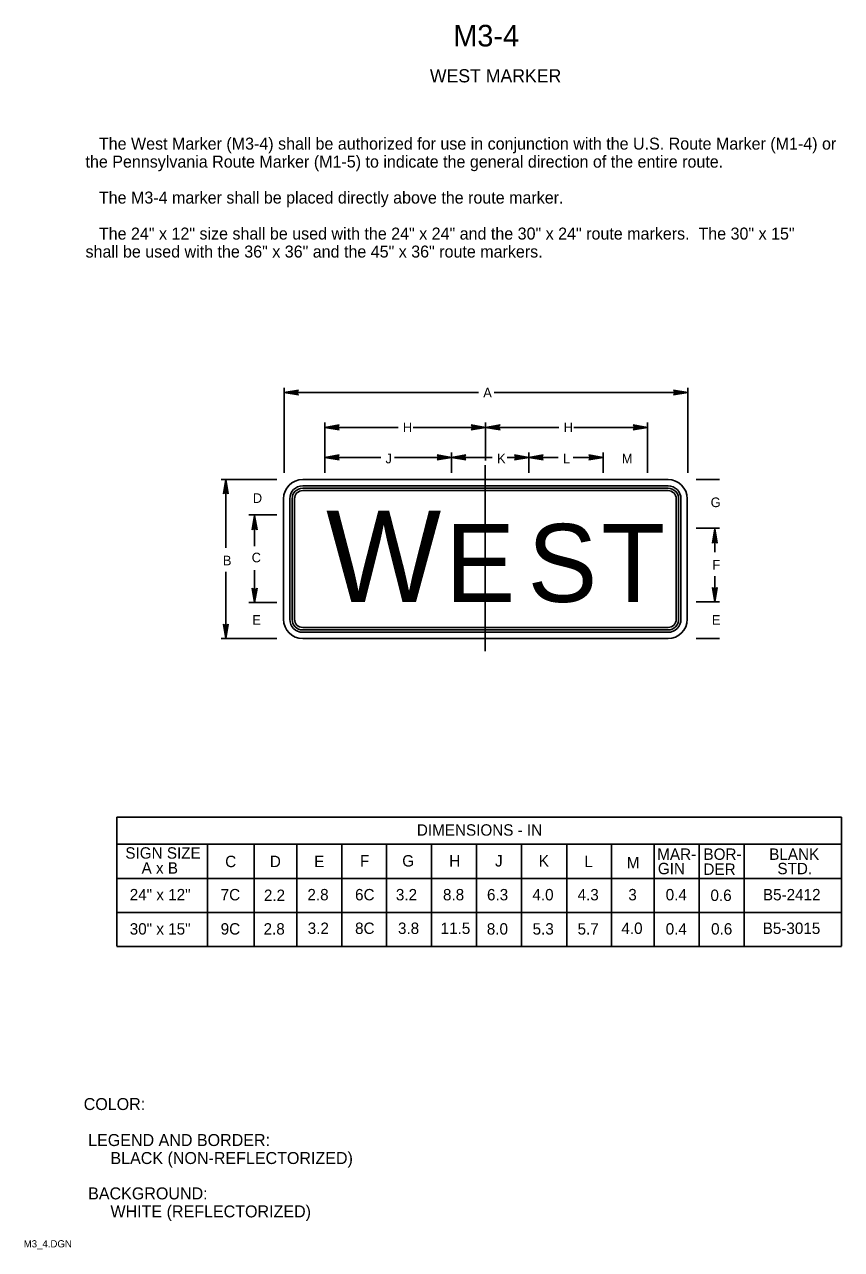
# Model space of a CAD drawing. Extents: x 0.013 to 0.183, y 0.004 to 0.259.
import ezdxf

# ---------------------------------------------------------------- set-up
doc = ezdxf.new("R2010")
doc.units = 0
doc.layers.add('1', color=7, linetype='Continuous')
doc.layers.add('3', color=7, linetype='Continuous')

# ---------------------------------------------------------------- blocks, each defined once
blk = doc.blocks.new('RARROW')
at = {"layer": '3'}
for p, q in [((-2.156, 0.285), (-2.2665, 0.384625)), ((-2.2665, 0.384625), (0, 0)), ((0, 0), (-2.2665, -0.379125)), ((-2.156, 0.285), (-2.075625, 0.12075)), ((0, 0), (-2.156, 0.285)), ((-2.14975, -0.2705), (0, 0)), ((-2.075625, 0.12075), (0, 0)), ((0, 0), (-2.074, -0.108)), ((-2.2665, -0.379125), (-2.14975, -0.2705)), ((-2.074, -0.108), (-2.14975, -0.2705))]:
    blk.add_line(p, q, dxfattribs=at)

msp = doc.modelspace()

# ---------------------------------------------------------------- linework, layer by layer
at = {"layer": '3'}
for p, q in [((0.06675, 0.16575), (0.06675, 0.1835)), ((0.10725, 0.1825), (0.06675, 0.1825)), ((0.1105, 0.1825), (0.15088, 0.1825)), ((0.15088, 0.16575), (0.15088, 0.1835)), ((0.07525, 0.16575), (0.07525, 0.17625)), ((0.10875, 0.16837), (0.10875, 0.17625)), ((0.1425, 0.16575), (0.1425, 0.17625)), ((0.0905, 0.17525), (0.07525, 0.17525)), ((0.09362, 0.17525), (0.10875, 0.17525)), ((0.124, 0.17525), (0.10875, 0.17525)), ((0.12713, 0.17525), (0.1425, 0.17525)), ((0.08688, 0.169), (0.07525, 0.169)), ((0.08975, 0.169), (0.10163, 0.169)), ((0.10163, 0.16575), (0.10163, 0.17)), ((0.11013, 0.169), (0.10163, 0.169)), ((0.11325, 0.169), (0.11775, 0.169)), ((0.11775, 0.16575), (0.11775, 0.17)), ((0.12387, 0.169), (0.11775, 0.169)), ((0.127, 0.169), (0.13325, 0.169)), ((0.12925, 0.169), (0.13325, 0.169)), ((0.13325, 0.16575), (0.13325, 0.17)), ((0.10862, 0.16737), (0.10862, 0.12862)), ((0.06525, 0.16437), (0.05362, 0.16437)), ((0.05462, 0.15013), (0.05462, 0.16437)), ((0.07063, 0.16437), (0.14675, 0.16437)), ((0.15263, 0.16437), (0.1575, 0.16437)), ((0.07063, 0.16307), (0.14675, 0.16307)), ((0.07063, 0.16257), (0.14675, 0.16257)), ((0.07063, 0.16207), (0.14675, 0.16207)), ((0.06663, 0.13525), (0.06663, 0.16037)), ((0.06793, 0.13525), (0.06793, 0.16037)), ((0.06843, 0.13525), (0.06843, 0.16037)), ((0.06893, 0.13525), (0.06893, 0.16037)), ((0.14845, 0.16037), (0.14845, 0.13525)), ((0.14895, 0.16037), (0.14895, 0.13525)), ((0.14945, 0.16037), (0.14945, 0.13525)), ((0.15075, 0.16037), (0.15075, 0.13525)), ((0.06525, 0.157), (0.05938, 0.157)), ((0.06062, 0.153), (0.06062, 0.157)), ((0.06062, 0.1505), (0.06062, 0.157)), ((0.15263, 0.15425), (0.1575, 0.15425)), ((0.1565, 0.15038), (0.1565, 0.15438)), ((0.1565, 0.14925), (0.1565, 0.15425)), ((0.06062, 0.1455), (0.06062, 0.13887)), ((0.05462, 0.14513), (0.05462, 0.13125)), ((0.1565, 0.14425), (0.1565, 0.139)), ((0.1565, 0.143), (0.1565, 0.139)), ((0.06062, 0.14288), (0.06062, 0.13887)), ((0.06525, 0.13875), (0.05938, 0.13875)), ((0.15263, 0.13887), (0.1575, 0.13887)), ((0.14675, 0.13355), (0.07063, 0.13355)), ((0.14675, 0.13305), (0.07063, 0.13305)), ((0.06525, 0.13125), (0.05362, 0.13125)), ((0.06475, 0.13125), (0.05963, 0.13125)), ((0.14675, 0.13255), (0.07063, 0.13255)), ((0.14675, 0.13125), (0.07063, 0.13125)), ((0.15263, 0.13125), (0.1575, 0.13125)), ((0.03187, 0.094), (0.18288, 0.094)), ((0.03187, 0.094), (0.03187, 0.06713)), ((0.18288, 0.094), (0.18288, 0.06713)), ((0.18289, 0.08838), (0.03189, 0.08838)), ((0.05077, 0.08838), (0.05077, 0.06708)), ((0.0605, 0.08837), (0.0605, 0.06713)), ((0.06938, 0.08837), (0.06938, 0.06713)), ((0.07875, 0.08837), (0.07875, 0.06713)), ((0.08812, 0.08837), (0.08812, 0.06713)), ((0.0975, 0.08837), (0.0975, 0.06713)), ((0.10687, 0.08837), (0.10687, 0.06713)), ((0.11625, 0.08837), (0.11625, 0.06713)), ((0.12563, 0.08837), (0.12563, 0.06713)), ((0.135, 0.08837), (0.135, 0.06713)), ((0.14389, 0.08838), (0.14389, 0.06708)), ((0.15327, 0.08838), (0.15327, 0.06708)), ((0.16264, 0.08838), (0.16264, 0.06708)), ((0.18288, 0.08128), (0.03187, 0.08128)), ((0.18289, 0.07418), (0.03189, 0.07418)), ((0.18289, 0.06708), (0.03189, 0.06708))]:
    msp.add_line(p, q, dxfattribs=at)
for centre, radius, start, end in [((0.07063, 0.16037), 0.004, 90, 180), ((0.14675, 0.16037), 0.004, 0, 90), ((0.07063, 0.16037), 0.0027, 90, 180), ((0.07063, 0.16037), 0.0022, 90, 180), ((0.07063, 0.16037), 0.0017, 90, 180), ((0.14675, 0.16037), 0.0027, 0, 90), ((0.14675, 0.16037), 0.0022, 0, 90), ((0.14675, 0.16037), 0.0017, 0, 90), ((0.07063, 0.13525), 0.004, 180, 270), ((0.07063, 0.13525), 0.0027, 180, 270), ((0.07063, 0.13525), 0.0022, 180, 270), ((0.07063, 0.13525), 0.0017, 180, 270), ((0.14675, 0.13525), 0.004, 270, 0), ((0.14675, 0.13525), 0.0027, 270, 0), ((0.14675, 0.13525), 0.0017, 270, 0), ((0.14675, 0.13525), 0.0022, 270, 0)]:
    msp.add_arc(centre, radius, start, end, dxfattribs=at)

# ---------------------------------------------------------------- block references
at = {"layer": '3', "xscale": 0.0013236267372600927, "yscale": 0.001309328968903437}
for p, rotation in [((0.06675, 0.1825), 180), ((0.07525, 0.17525), 180), ((0.10875, 0.17525), 180), ((0.07525, 0.169), 180), ((0.10163, 0.169), 180), ((0.11775, 0.169), 180), ((0.05462, 0.16437), 90), ((0.06062, 0.15688), 90), ((0.1565, 0.15413), 90), ((0.1565, 0.15413), 90), ((0.06062, 0.13875), -90), ((0.1565, 0.13887), -90), ((0.05462, 0.13125), -90)]:
    msp.add_blockref('RARROW', p, dxfattribs=dict(at, rotation=rotation))
for p in [(0.15088, 0.1825), (0.10875, 0.17525), (0.1425, 0.17525), (0.10163, 0.169), (0.11775, 0.169), (0.13325, 0.169)]:
    msp.add_blockref('RARROW', p, dxfattribs=at)

# ---------------------------------------------------------------- texts
at = {"layer": '1'}
for s, height, p in [('M3-4', 0.0045, (0.102, 0.25462)), ('WEST MARKER', 0.0027503, (0.09713, 0.24713)), ('   The West Marker (M3-4) shall be authorized for use in conjunction with the U.S. Route Marker (M1-4) or', 0.00249975, (0.02538, 0.23312)), ('the Pennsylvania Route Marker (M1-5) to indicate the general direction of the entire route.', 0.0024998, (0.02538, 0.22937)), ('   The M3-4 marker shall be placed directly above the route marker.', 0.0024998, (0.02538, 0.22188)), ('   The 24" x 12" size shall be used with the 24" x 24" and the 30" x 24" route markers.  The 30" x 15" ', 0.00249975, (0.02538, 0.21438)), ('shall be used with the 36" x 36" and the 45" x 36" route markers.', 0.0024998, (0.02538, 0.21063)), ('COLOR:', 0.0025, (0.025, 0.033)), (' LEGEND AND BORDER:', 0.0024998, (0.025, 0.0255)), ('      BLACK (NON-REFLECTORIZED)', 0.0024998, (0.025, 0.02175)), (' BACKGROUND:', 0.0024998, (0.025, 0.01438)), ('      WHITE (REFLECTORIZED)', 0.0024998, (0.025, 0.01063)), ('M3_4.DGN', 0.0015, (0.0125, 0.00438))]:
    msp.add_text(s, height=height, dxfattribs=at).set_placement(p)
at = {"layer": '3'}
for s, height, p in [('A', 0.002, (0.10825, 0.1815)), ('H', 0.002, (0.0915, 0.17425)), ('H', 0.002, (0.125, 0.17425)), ('J', 0.002, (0.08788, 0.16775)), ('K', 0.002, (0.11113, 0.16775)), ('L', 0.002, (0.12487, 0.16775)), ('M', 0.002, (0.13712, 0.16775)), ('D', 0.002, (0.06025, 0.1595)), ('G', 0.002, (0.15563, 0.15863)), ('W', 0.019, (0.0755, 0.13887)), ('E', 0.01625, (0.10038, 0.13887)), ('S', 0.01625, (0.1175, 0.13887)), ('T', 0.01625, (0.13287, 0.13887)), ('B', 0.002, (0.054, 0.1465)), ('C', 0.002, (0.06, 0.14713)), ('F', 0.002, (0.156, 0.14563)), ('E', 0.002, (0.06012, 0.13412)), ('E', 0.002, (0.15588, 0.13412)), ('DIMENSIONS - IN', 0.0023752, (0.09442, 0.09017)), ('SIGN SIZE', 0.002375, (0.03368, 0.08538)), ('MAR-', 0.002375, (0.1445, 0.08513)), ('BOR-', 0.002375, (0.15413, 0.08513)), ('BLANK', 0.002375, (0.16783, 0.08513)), ('A x B', 0.002375, (0.03706, 0.08225)), ('C', 0.00238, (0.05448, 0.08361)), ('D', 0.00238, (0.06378, 0.08361)), ('E', 0.00238, (0.07303, 0.08361)), ('F', 0.00238, (0.08256, 0.08374)), ('G', 0.00238, (0.09137, 0.08374)), ('H', 0.00238, (0.10116, 0.08374)), ('J', 0.00238, (0.11071, 0.08374)), ('K', 0.00238, (0.11981, 0.08374)), ('L', 0.00238, (0.12934, 0.08361)), ('M', 0.00238, (0.13814, 0.08336)), ('GIN', 0.002375, (0.14463, 0.08213)), ('DER', 0.002375, (0.15413, 0.082)), ('STD.', 0.002375, (0.16954, 0.08213)), ('24" x 12"', 0.002375, (0.03459, 0.07669)), ('7C', 0.002375, (0.05354, 0.07669)), ('2.2', 0.002375, (0.06254, 0.07656)), ('2.8', 0.002375, (0.07161, 0.07669)), ('6C', 0.002375, (0.08154, 0.07669)), ('3.2', 0.002375, (0.09004, 0.07669)), ('8.8', 0.002375, (0.09986, 0.07669)), ('6.3', 0.002375, (0.10903, 0.07669)), ('4.0', 0.002375, (0.11849, 0.07669)), ('4.3', 0.002375, (0.1279, 0.07669)), ('3', 0.00238, (0.13847, 0.07669)), ('0.4', 0.002375, (0.14626, 0.07669)), ('0.6', 0.002375, (0.15559, 0.07656)), ('B5-2412', 0.002375, (0.16652, 0.07669)), ('30" x 15"', 0.002375, (0.03459, 0.06956)), ('9C', 0.002375, (0.05354, 0.06956)), ('2.8', 0.002375, (0.06248, 0.06956)), ('3.2', 0.002375, (0.07167, 0.06969)), ('8C', 0.002375, (0.08154, 0.06969)), ('3.8', 0.002375, (0.09048, 0.06969)), ('11.5', 0.002375, (0.09937, 0.06969)), ('8.0', 0.002375, (0.10899, 0.06956)), ('5.3', 0.002375, (0.11853, 0.06956)), ('5.7', 0.002375, (0.1279, 0.06956)), ('4.0', 0.002375, (0.13703, 0.06969)), ('0.4', 0.002375, (0.14626, 0.06956)), ('0.6', 0.002375, (0.15572, 0.06956)), ('B5-3015', 0.002375, (0.16647, 0.06969))]:
    msp.add_text(s, height=height, dxfattribs=at).set_placement(p)

doc.saveas('drawing.dxf')
